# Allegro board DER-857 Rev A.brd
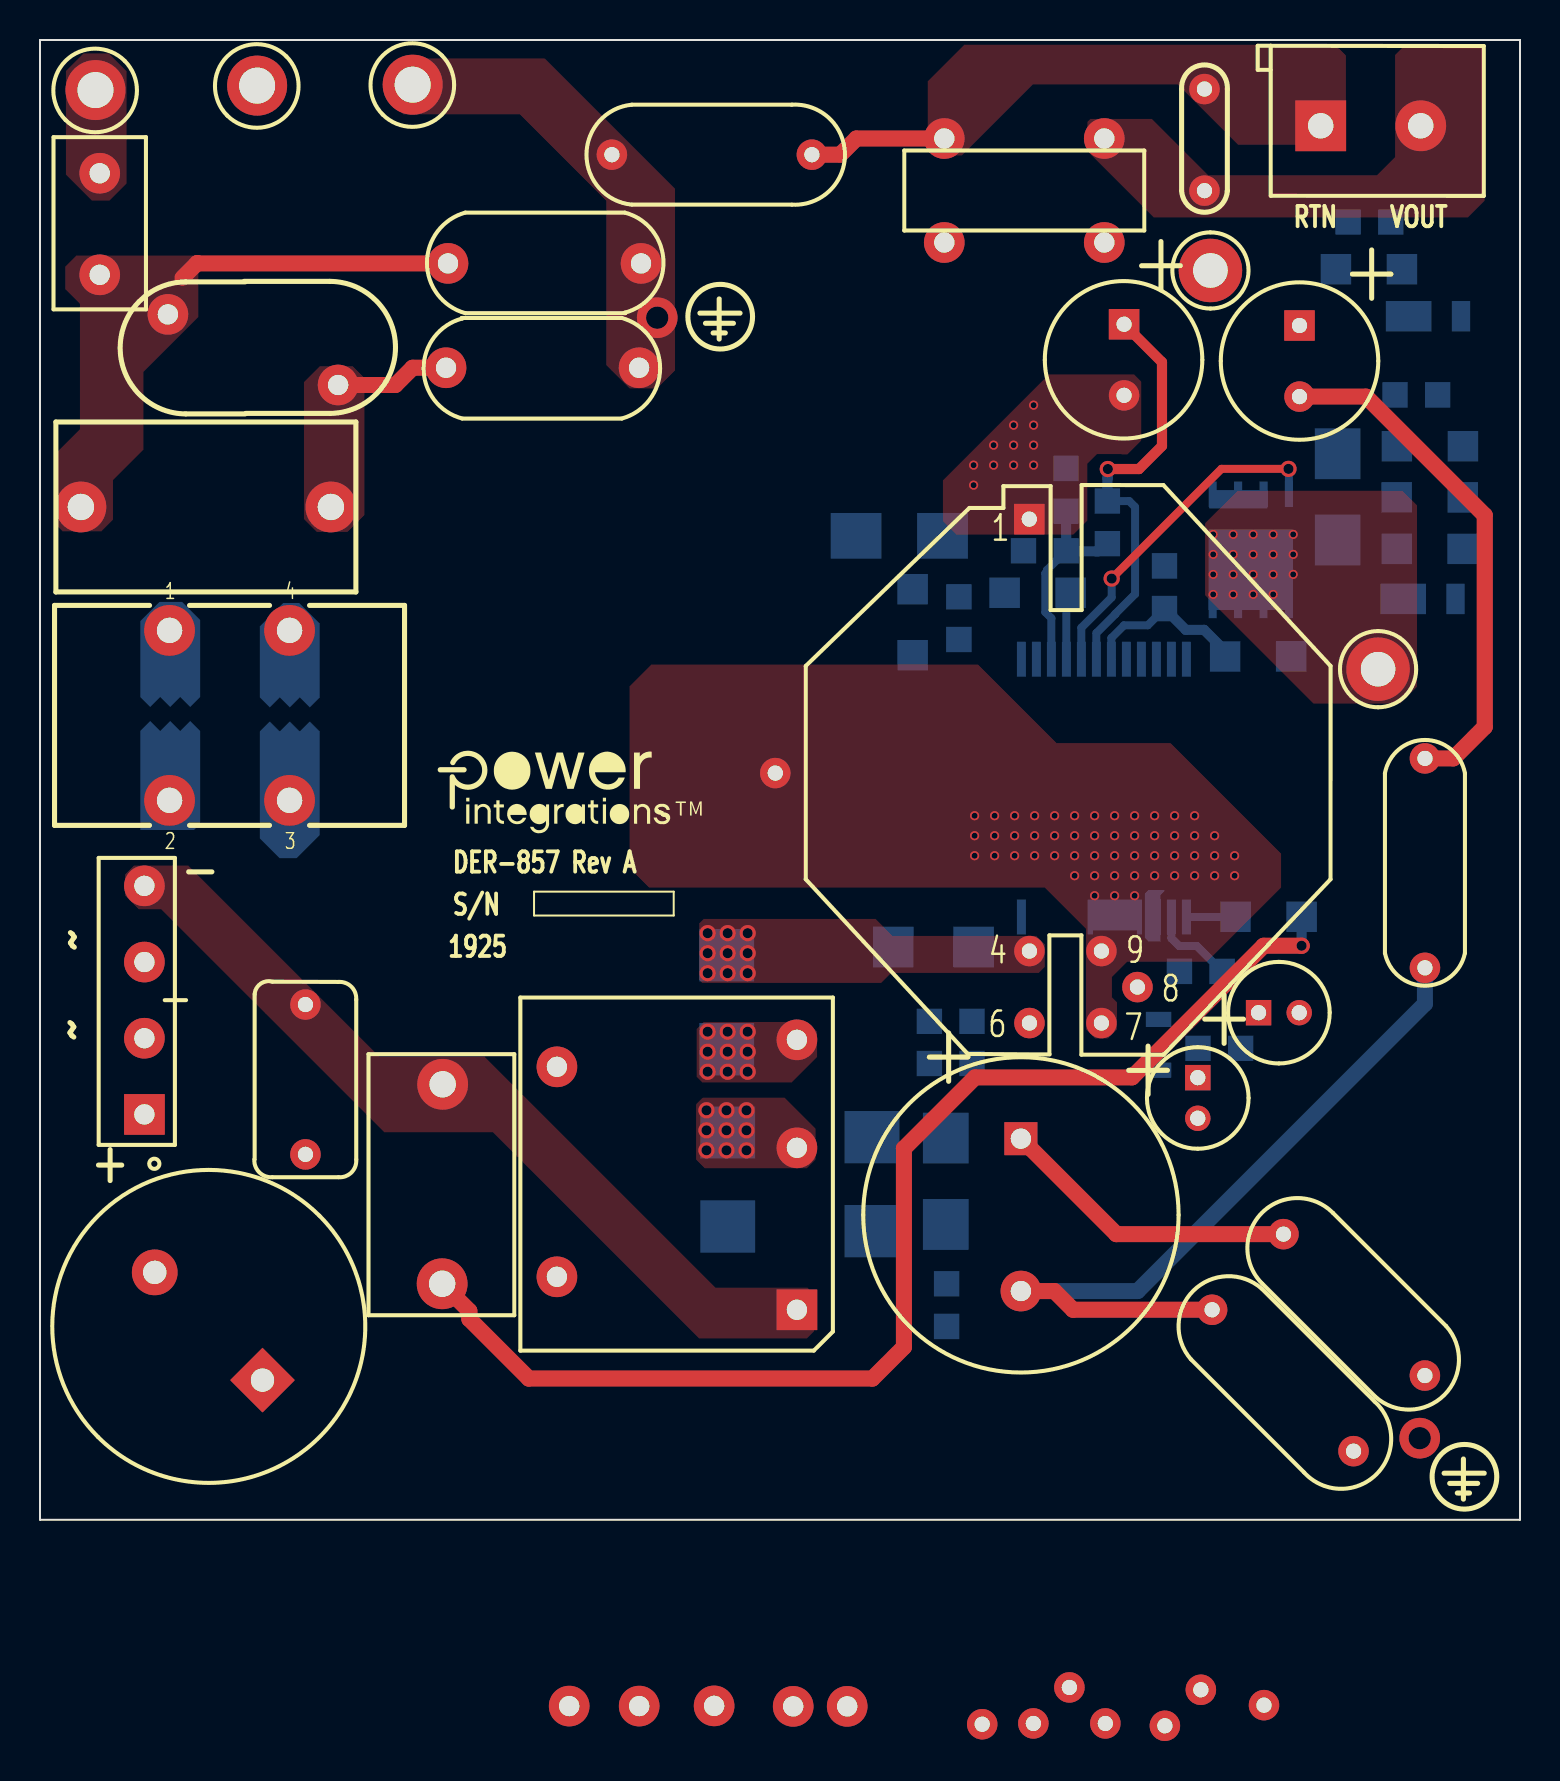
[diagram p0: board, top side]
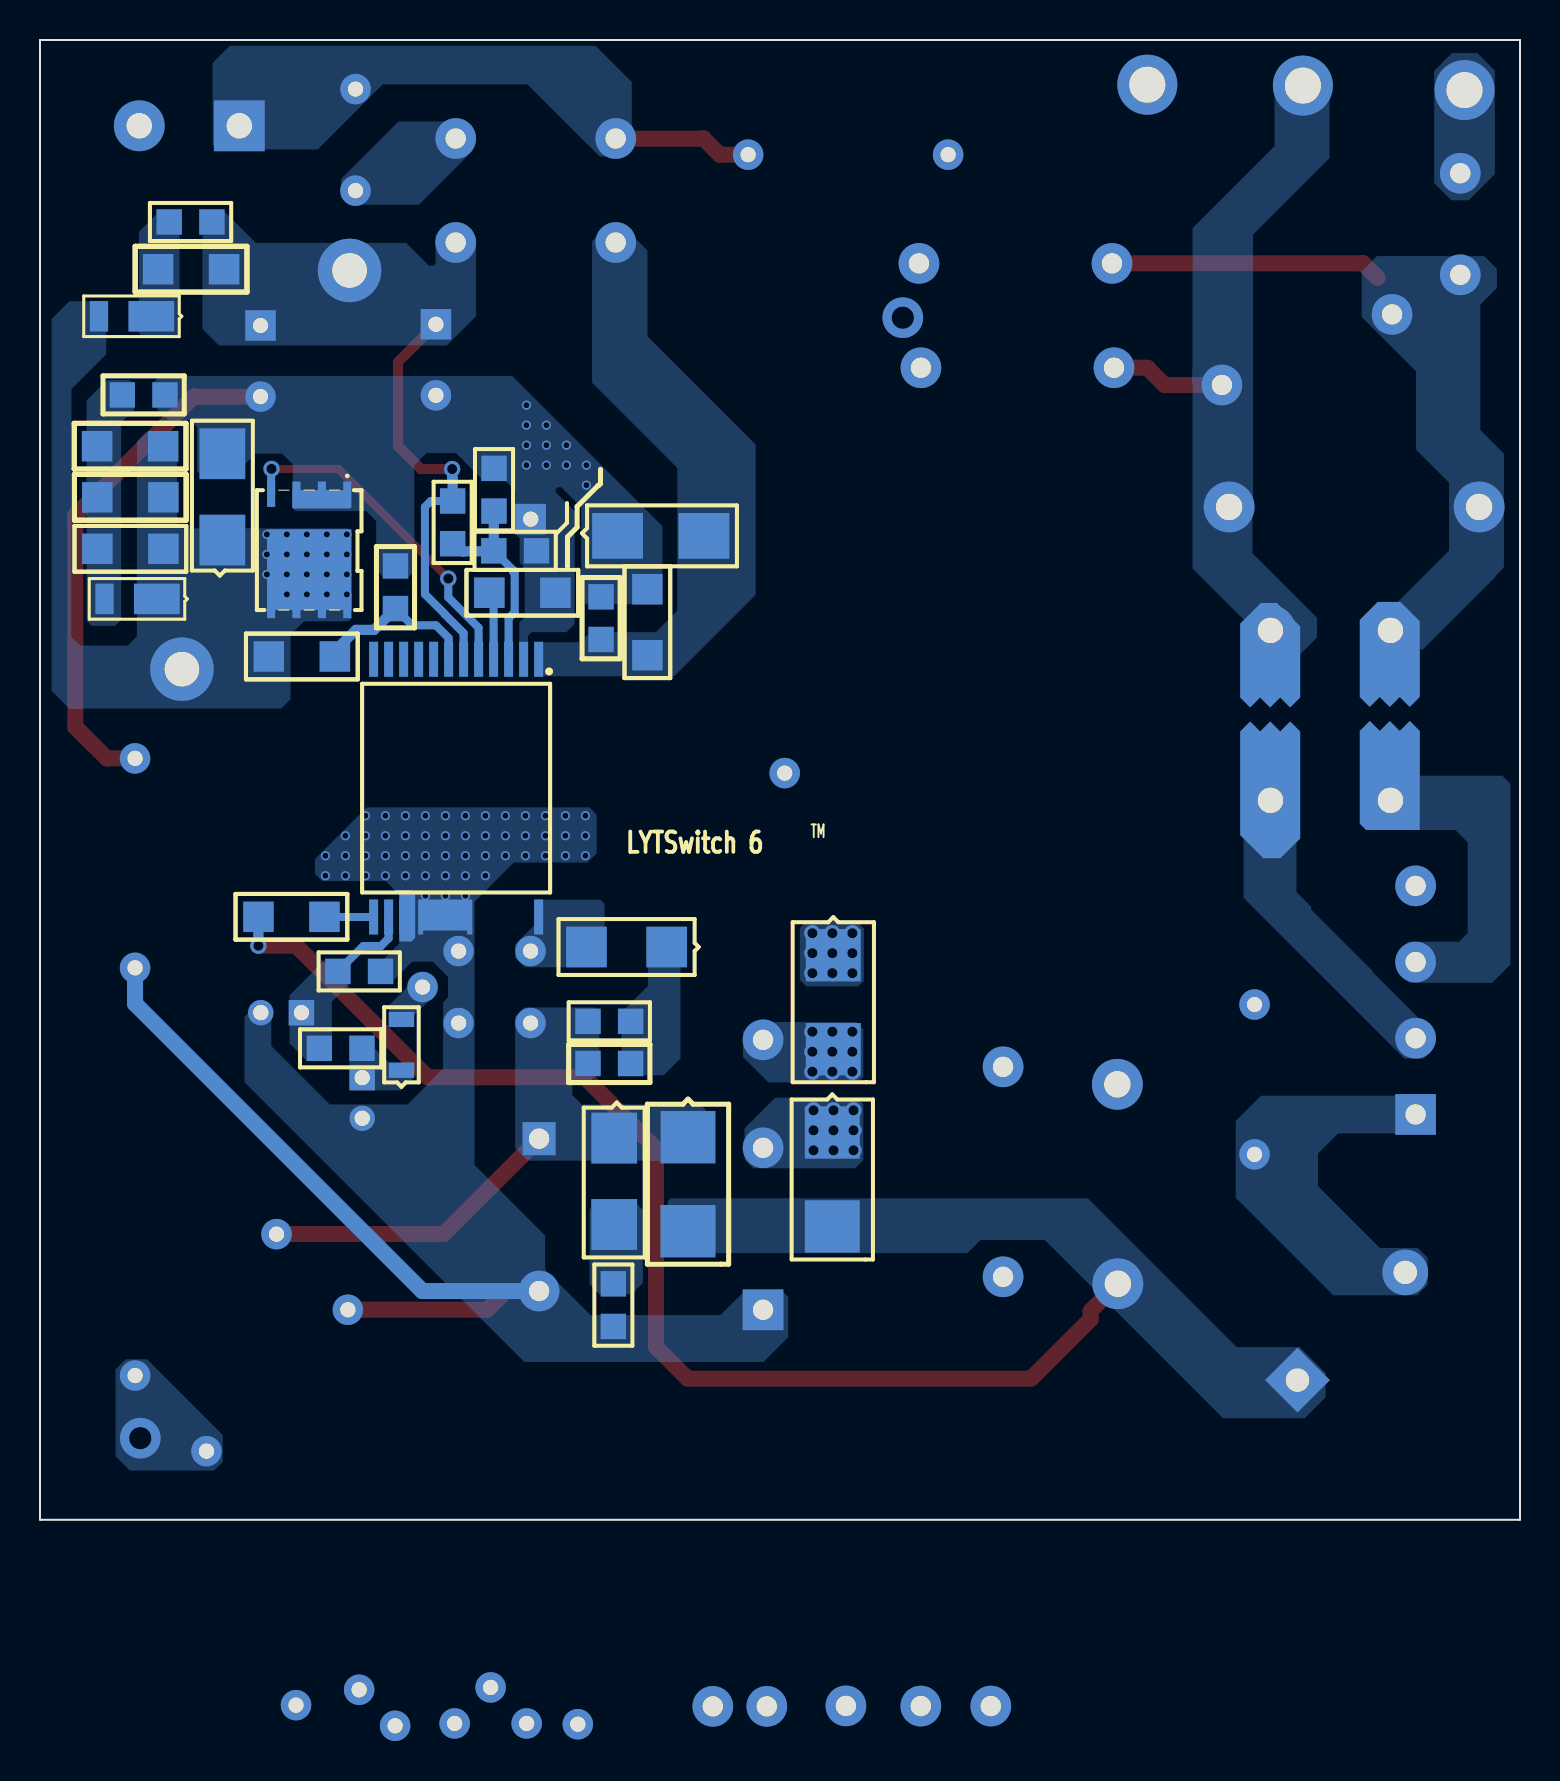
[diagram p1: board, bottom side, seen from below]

Outline 74 x 74 mm; copper layers: TOP, BOTTOM. Coordinates in mm from the lower left corner of the outline.
Outline path: 0,74 74,74 74,0 0,0 0,74

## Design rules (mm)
constraint set DEFAULT: min track width 0.508

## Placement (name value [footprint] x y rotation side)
BR1  UG4KB60TB  [PIDAXBRIDGED3K]  5.22 20.27 90 top
C1  330 nF  [PINP_XCAPRAD15X8P5X14HD040]  14.54 50.65 180 top
C3  330 nF  [PINPCR511X300LS393D40]  20.13 11.78 90 top
C4  100 uF  [PIPOLCAPCLYD630LS300040]  49.05 19.06 270 top
C9  1 nF  [PISMC0805]  44.47 24.93 0 bottom
C10  10 uF  [PIPOLCAPCLYD200LS80030]  57.89 22.11 270 top
C11  0.47 uF  [PIPOLCAPCLYD200LS80030]  60.93 25.36 0 top
C12  2200 pF  [PINPCAPRAD9P0D10P0LS030#2]  69.25 27.84 90 top
C13  2.2 uF  [PISMC1206]  48.23 46.36 0 bottom
C14  2.2 nF  [PISMC0805]  69.88 56.25 180 bottom
C16  270 uF  [PIPOLCAPCLYD320LS140030]  54.2 59.78 270 top
C18  270 uF  [PIPOLCAPCLYD320LS140030]  62.98 59.72 270 top
C19  330 pF  [PISMC0805]  49.17 48.45 0 bottom
C34  68 pF  [PINPYCAPRAD470X210LS380040]  20.3 57.61 0 top
C35  68 pF  [PINPYCAPRAD470X210LS380040]  30.05 62.83 180 top
C37  1 nF  [PINPCAPRAD200X100200030]  58.22 66.47 90 top
C41  2200 pF  [PINPCAPRAD9P0D10P0LS030]  38.59 68.27 180 top
C42  2200 pF  [PINPCAPRAD9P0D10P0LS030]  62.17 14.28 315 top
C43  2200 pF  [PINPCAPRAD9P0D10P0LS030]  65.68 3.43 135 top
C44  100 nF  [PISMC1206]  64.8 62.54 0 bottom
C45  220 nF  [PI_NP_CAP_RAD386X197X295X030]  13.27 18.27 90 top
C46  10 nF  [PISMC0805]  59.11 27.42 180 bottom
C48  100 pF  [PISMC0805]  56.23 47.7 270 bottom
D1  ES2G-13-F  [PISMDO214AA12]  34.39 19.37 270 bottom
D7  BAV21WS-7-F  [PISMSOD323]  55.93 22.48 90 bottom
D8  S1J-13-F  [PISMDSMA]  42.66 28.64 0 bottom
D16  ES2G-13-F  [PISMDO214AA12]  41.6 19.13 270 bottom
D17  ES2G-13-F  [PISMDO214AA12]  34.33 28.23 270 bottom
D18  STPS2150A  [PISMDO214AC12]  64.88 48.99 90 bottom
D21  B340A-13-F  [PISMDO214AC12]  45.12 49.2 180 bottom
D22  DFLR1200-7  [PISMDDFLR120012]  68.41 60.18 180 bottom
D23  DFLR1200-7  [PISMDDFLR120012]  68.13 46.05 180 bottom
E  GRN  [PITPKEYSTONE125X125]  18.63 71.76 315 top
F1  3.15 A  [PI_RST_MICROFUSE]  2.99 67.34 270 top
FL1  Hole_70mils  [PI_HOLE_70MIL]  58.52 62.45 0 top
FL2  Hole_70mils  [PI_HOLE_70MIL]  66.9 42.51 0 top
J2  TERMINAL BLOCK  [PI_TERM_BLOCK_2PIN_LS200]  64.04 69.71 270 top
L  WHT  [PITPKEYSTONE125X125]  10.86 71.72 315 top
L1  18mH  [PI_CMC_18MH_SUMIDA]  6.48 44.48 0 top
L4  200 uH  [PI_TOROID_DER742CMCL4]  45.21 63.07 180 top
L5  560 uh  [PI_CHOKE_RL5480-5_D2]  11.12 6.98 135 top
N  BLK  [PITPKEYSTONE125X125]  2.77 71.5 315 top
NOREF  -  []  0 0 90 top
NOREF#2  -  []  0 74 0 top
NOREF#3  -  []  -28.46 39.35 0 top
Q1  AON6250  [PISMPQFN5X6B]  58.64 51.28 0 bottom
R4  3.9 M  [PISMR1206]  59.78 30.15 0 bottom
R17  680 k  [PISMR0805]  46.6 22.82 180 bottom
R18  10 k  [PISMR0805]  57.9 23.57 0 bottom
R22  47  [PISMR1206]  59.26 43.17 0 bottom
R23  30  [PISMR1206]  67.83 48.55 0 bottom
R24  0.025  [PISMR1206]  43.63 43.23 90 bottom
R29  169 k  [PISMR0805]  53.37 50.94 270 bottom
R30  9.31 k  [PISMR0805]  51.3 50.44 90 bottom
R47  10 k  [PISMR0805]  45.33 11.8 270 bottom
R51  0.02  [PISMR0805]  45.94 44.02 90 bottom
R52  100 k  [PISMR0805]  65.41 64.9 0 bottom
R53  30  [PISMR1206]  71.14 51.13 180 bottom
R54  30  [PISMR1206]  71.15 53.69 180 bottom
RV1  140 Vac  [PIDISC500X225LS335X140040]  6.4 60.28 0 top
T1  EE19  [PI_BOBBIN_EE19_10P]  37.85 10.5 180 top
T2  RM10  [PI_BOBBIN_RM-10_12P_CLP]  49.46 50.04 270 top
U4  LYT6079C  [PI_IC_INSOP_24D]  49.07 43.03 270 bottom
VR2  BZG04-220-HM3-08  [PISMDO214AC12]  45.29 19.09 270 bottom

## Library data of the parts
BR1 = DISCRETE BRIDGE_+~~-: alternate symbols: (pidaxbridgeD3K_horz)
C1 = CAP NP: alternate symbols: (pinp_xcaprad15x8p5x14Hd040H)
C3 C9 C12-C14 C19 C34 C35 C37 C41-C46 C48 = CAP NP
C4 = CAP POL: alternate symbols: (pipolcapclyd7p5ls16x21p5D040h)
C10 = CAP POL: alternate symbols: (pipolcapclyd200ls80030h)
C11 = CAP POL: alternate symbols: (pipolcapclyd5p0x12p5ls2p0d30h)
C16 C18 = CAP POL: alternate symbols: (pipolcapclyd320ls140d30h750)
D1 D7 D8 D16 D17 D22 D23 = DIODE
D18 D21 = DIODE SCHOTTKY
E L N = TESTPOINT
F1 = FUSE: alternate symbols: (pirstmicrofusehoz)
FL1 FL2 = FlyingLead
J2 = CON2
L1 = TORRID 4P_12_43a: alternate symbols: (pi_CMC_18mH_Sumida_H)
L4 = TORRID 4P_13_24
L5 = INDUCTOR_DOT2: alternate symbols: (pi_choke_RL5480-5H_d2)
Q1 = FET_N_SGD_123_4_5678
R4 R17 R18 R22-R24 R29 R30 R47 R51-R54 = R
RV1 = VARISTOR
T1 = BEE19_10P/TF1939
T2 = BRM10_12P/PINS
U4 = LYT6
VR2 = DIODE_ZENER

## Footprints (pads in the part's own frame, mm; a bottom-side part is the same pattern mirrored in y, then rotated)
PI_BOBBIN_EE19_10P
  rect 2.032x2.032 hole 1.016: 1(0,0)
  round 2.032 hole 1.016: 2(-2.514,19.831) 3(0.186,19.831) 4(0,-8.1) 5(4.14,19.807) 6(0,-13.5) 7(12,-12.15) 8(11.387,19.817) 9(7.887,19.817) 10(12,-1.65)
PI_BOBBIN_RM-10_12P_CLP
  rect 1.524x1.524 hole 0.762: 1(0,0)
  round 1.524 hole 0.762: 2(60.34,6.779) 3(58.539,8.578) 4(21.6,0.008) 5(60.264,-2.355) 6(25.199,0.008) 7(25.199,3.607) 8(23.401,5.408) 9(21.6,3.607) 10(60.223,3.802) 11(58.422,2.004) 12(60.223,0.203) 13(59.309,11.735) 14(12.7,-12.7)
PI_CHOKE_RL5480-5_D2
  rect 2.286x2.286 hole 1.168: 1(0,0)
  round 2.286 hole 1.168: 2(7.62,0)
PI_CMC_18MH_SUMIDA
  round 2.54 hole 1.27: 1(0,0) 2(0,-8.5) 3(6,-8.5) 4(6,0)
PI_HOLE_70MIL
  round 3.175 hole 1.727: 1(0,0.025)
PI_IC_INSOP_24D
  rect 1.75x0.45 smd: 1(0,0) 2(0,-0.75) 3(0,-1.5) 4(0,-2.25) 5(0,-3) 6(0,-3.75) 7(0,-4.5) 8(0,-5.25) 9(0,-6) 10(0,-6.75) 11(0,-7.5) 12(0,-8.25) 13(12.89,-8.25) 14(12.89,-7.5) 15(12.89,-6.75) 24(12.89,0)
  custom 0.438x0.438 smd: 16(12.89,-4.67)
PI_NP_CAP_RAD386X197X295X030
  round 1.524 hole 0.762: 1(0,0) 2(7.493,0)
PI_RST_MICROFUSE
  round 2.032 hole 1.016: 1(0,0) 2(5.08,0)
PI_TERM_BLOCK_2PIN_LS200
  rect 2.54x2.54 hole 1.27: 1(0,0)
  round 2.54 hole 1.27: 2(0,5.001)
PI_TOROID_DER742CMCL4
  round 2.032 hole 1.016: 1(0,-0.8) 2(-8,-0.8) 3(0,-6) 4(-8,-6)
PIDAXBRIDGED3K
  rect 2.032x2.032 hole 1.016: 1(0,0)
  round 2.032 hole 1.016: 2(3.81,0) 3(7.62,0) 4(11.43,0)
PIDISC500X225LS335X140040
  round 2.032 hole 1.016: 1(0,0) 2(8.509,-3.531)
PINP_XCAPRAD15X8P5X14HD040
  round 2.54 hole 1.321: 1(0,0) 2(12.5,0)
PINPCAPRAD9P0D10P0LS030
  round 1.524 hole 0.762: 1(0,0) 2(10,0)
PINPCAPRAD9P0D10P0LS030#2
  round 1.524 hole 0.762: 1(-0.236,0) 2(10.236,0)
PINPCAPRAD200X100200030
  round 1.524 hole 0.762: 1(0,0) 2(5.08,0)
PINPCR511X300LS393D40
  round 2.54 hole 1.321: 1(0.025,0.025) 2(10,0)
PINPYCAPRAD470X210LS380040
  round 2.032 hole 1.016: 1(0,0) 2(9.652,0)
PIPOLCAPCLYD200LS80030
  rect 1.27x1.27 hole 0.762: 1(0,0)
  round 1.27 hole 0.762: 2(2.032,0)
PIPOLCAPCLYD320LS140030
  rect 1.524x1.524 hole 0.762: 1(0,0)
  round 1.524 hole 0.762: 2(3.556,0)
PIPOLCAPCLYD630LS300040
  rect 1.651x1.651 hole 1.016: 1(0,0)
  round 2.032 hole 1.016: 2(7.62,0)
PISMC0805
  rect 1.27x1.27 smd: 1(0,0) 2(2.134,0)
PISMC1206
  rect 1.524x1.524 smd: 1(0,0) 2(3.302,0)
PISMDDFLR120012
  rect 2.286x1.524 smd: 1(-0.025,0)
  rect 0.914x1.524 smd: 2(-2.642,0)
PISMDO214AA12
  rect 2.616x2.743 smd: 1(0,0) 2(4.699,0)
PISMDO214AC12
  rect 2.54x2.286 smd: 1(0,0) 2(4.318,0)
PISMDSMA
  rect 2.032x2.032 smd: 1(0,0) 2(4.013,0)
PISMPQFN5X6B
  rect 0.406x1.27 smd: 1(0,0) 2(1.27,0) 3(2.54,0) 4(3.81,0)
  rect 0.406x1.219 smd: 5(3.81,5.588) 6(2.54,5.588) 7(1.27,5.588) 8(0,5.588)
PISMR0805
  rect 1.27x1.27 smd: 1(0,0) 2(2.134,0)
PISMR1206
  rect 1.524x1.524 smd: 1(0,0) 2(3.302,0)
PISMSOD323
  rect 0.762x1.27 smd: 1(0,0) 2(2.54,0)
PITPKEYSTONE125X125
  round 3 hole 1.8: 1(0,0)

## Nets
GND: C12.2 C13.1 C14.2 C16.2 C18.2 C19.1 C48.1 D18.2 D21.1 Q1.1 Q1.2 Q1.3(S3) R24.2 R30.2 R51.2 T2.1 U4.2
GND_EARTH: C34.2 C35.1 C41.2 C42.2 C43.1 E.1
NC8: U4.8
NC9: U4.9
NC10: U4.10
NC11: U4.11
NC12: U4.12
NC15: U4.15
N10967118: C10.1 D7.1 R18.1
N10967272: D8.2 D17.1 T2.4 U4.24
N10967292: C4.1 C9.2 C42.1 D16.1 R17.1 T2.6 VR2.1
N10967352: C11.1 C46.1 R18.2 U4.14
N10967360: C19.2 R29.2 R30.1 U4.3
N10967588: C16.1 C18.1 C44.1 FL1.1 L4.2 R29.1 R52.1 U4.6
N10967640: D18.1 D22.2 D23.1 FL2.1 Q1.5 Q1.6 Q1.7 Q1.8 R22.2 R23.1 R53.2 R54.2
N10968210: C14.1 D23.2 R23.2 R53.1 R54.1
N10968562: BR1.4 C3.2 C4.2 C10.2 C11.2 C12.1 C43.2 C45.2 C46.2 R47.2 T1.1 T2.7 T2.9 T2.14 U4.16
N10971255: BR1.3(AC2) L1.2
N10975943: C9.1 D8.1 R17.2
N11015169: Q1.4 U4.5
N11207739: C1.1 C34.1 L.1 L1.4 RV1.2
N11207756: C1.2 C35.2 F1.2 L1.1 RV1.1
N11317958: R4.1 U4.13(VPIN)
N11319179: C13.2 U4.4
N11459390: C3.1 D1.2 D16.2 L5.1 R4.2
N11460031: BR1.1 C45.1 L5.2
N11465077: F1.1 N.1
N11478836: R47.1 VR2.2
N11926309: C37.2 C41.1 J2.1 L4.3
N11926313: C37.1 J2.2 L4.4
N11931425: D7.2 T2.8
N11945881: D21.2 L4.1 R24.1 R51.1 U4.1
N12237173: D17.2 T1.6
N12296601: BR1.2 L1.3
N12434563: C44.2 D22.1 R52.2
N12457252: D1.1 T1.4
N12494744: C48.2 R22.1 U4.7

Pads without a net: T1 2 3 5 7 8 9 10; T2 2 3 5 10 11 12 13

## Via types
v1: diameter 2.032, hole 1.118, TOP to BOTTOM, 2 vias
v2: diameter 0.813, hole 0.508, TOP to BOTTOM, 31 vias
v3: diameter 0.457, hole 0.305, TOP to BOTTOM, 81 vias

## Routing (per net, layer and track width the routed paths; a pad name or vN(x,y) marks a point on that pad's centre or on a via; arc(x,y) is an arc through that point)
GND: length 25.9
  TOP w0.8: C18.2 66.3,56.17 72.24,50.23 72.24,39.65 70.66,38.07 C12.2
  vias: v3(46.68,52.74) v3(46.68,51.74) v3(47.68,53.74) v3(47.68,52.74) v3(48.68,54.74) v3(48.68,53.74) v3(48.68,52.74) v3(49.68,55.74) v3(49.68,54.74) v3(49.68,53.74) v3(49.68,52.74)
GND_EARTH:
  vias: v1(30.86,60.11) v1(68.99,4.08)
N10967272:
  vias: v2(33.38,29.33) v2(33.38,28.33) v2(33.38,27.33) v2(34.38,29.33) v2(34.38,28.33) v2(34.38,27.33) v2(35.38,29.33) v2(35.38,28.33) v2(35.38,27.33)
N10967292: length 15.1
  TOP w0.8: C42.1 53.82,14.28 C4.1
N10967352: length 4.3
  BOTTOM w0.4: U4.14 56.57,29.08 56.95,28.69 57.84,28.69 C46.1
N10967360: length 10.2
  BOTTOM w0.4: C19.2 50.35,47.5 50.35,47.42 50.27,47.33 50.27,45.39 50.57,45.09 U4.3
  BOTTOM w0.508: R29.2 53.24,48.81 52.86,48.43 51.33,48.43 C19.2 51.31,50.43 R30.1
N10967588: length 21.6
  TOP w0.508: C16.1 56.1,57.89 56.1,53.7 54.95,52.54 v2(53.39,52.54)
  BOTTOM w0.4: U4.6 52.82,44.34 53.76,45.29 53.76,45.3 54.75,46.29 54.75,50.65 54.46,50.94 R29.1
  BOTTOM w0.508: R29.1 53.37,52.09 53.39,52.11 v2(53.39,52.54)
N10967640:
  vias: v3(58.66,49.28) v3(58.66,48.28) v3(58.66,47.28) v3(58.66,46.28) v3(59.66,49.28) v3(59.66,48.28) v3(59.66,47.28) v3(59.66,46.28) v3(60.66,49.28) v3(60.66,48.28) v3(60.66,47.28) v3(60.66,46.28) v3(61.66,49.28) v3(61.66,48.28) v3(61.66,47.28) v3(61.66,46.28) v3(62.66,49.28) v3(62.66,48.28) v3(62.66,47.28)
N10968562: length 37.9
  TOP w0.8: C43.2 51.65,10.5 50.72,11.44 C4.2
  BOTTOM w0.8: C4.2 54.88,11.44 69.25,25.8 C12.1
  vias: v3(46.73,35.21) v3(46.73,34.21) v3(46.73,33.21) v3(47.73,35.21) v3(47.73,34.21) v3(47.73,33.21) v3(48.73,35.21) v3(48.73,34.21) v3(48.73,33.21) v3(49.73,35.21) v3(49.73,34.21) v3(49.73,33.21) v3(50.73,35.21) v3(50.73,34.21) v3(50.73,33.21) v3(51.73,35.21) v3(51.73,34.21) v3(51.73,33.21) v3(51.73,32.21) v3(52.73,35.21) v3(52.73,34.21) v3(52.73,33.21) v3(52.73,32.21) v3(52.73,31.21) v3(53.73,35.21) v3(53.73,34.21) v3(53.73,33.21) v3(53.73,32.21) v3(53.73,31.21) v3(54.73,35.21) v3(54.73,34.21) v3(54.73,33.21) v3(54.73,32.21) v3(54.73,31.21) v3(55.73,35.21) v3(55.73,34.21) v3(55.73,33.21) v3(55.73,32.21) v3(56.73,35.21) v3(56.73,34.21) v3(56.73,33.21) v3(56.73,32.21) v3(57.73,35.21) v3(57.73,34.21) v3(57.73,33.21) v3(57.73,32.21) v3(58.73,34.21) v3(58.73,33.21) v3(58.73,32.21) v3(59.73,33.21) v3(59.73,32.21)
N11015169: length 17.1
  TOP w0.4: v2(62.42,52.55) 59.07,52.55 v2(53.58,47.07)
  BOTTOM w0.4: v2(62.42,52.55) 62.45,52.53 Q1.4 ; v2(53.58,47.07) 53.58,46.13 52.07,44.61 U4.5
N11207739: length 5.8
  TOP w0.8: RV1.2 17.77,56.75 18.63,57.61 C34.1
N11207756: length 13.6
  TOP w0.8: C35.2 7.88,62.83 7.88,62.82 7.86,62.84 7.12,62.11
N11317958: length 2.5
  BOTTOM w0.4: R4.1 59.68,30.15 59.67,30.14 U4.13
N11319179: length 3.4
  BOTTOM w0.4: U4.4 51.32,46.15 C13.2
N11459390: length 61.4
  TOP w0.8: C3.1 21.47,10.44 21.47,10.03 24.44,7.06 41.62,7.06 43.2,8.64 43.2,18.57 46.75,22.12 54.6,22.12 61.18,28.71 v2(63.08,28.71)
  BOTTOM w0.508: R4.2 v2(63.08,28.71)
N11926309: length 7
  TOP w0.8: C41.1 40.01,68.27 40.82,69.07 L4.3
N12237173:
  vias: v2(33.38,24.41) v2(33.38,23.41) v2(33.38,22.41) v2(34.38,24.41) v2(34.38,23.41) v2(34.38,22.41) v2(35.38,24.41) v2(35.38,23.41) v2(35.38,22.41)
N12457252:
  vias: v2(33.32,20.48) v2(33.32,19.48) v2(33.32,18.48) v2(34.32,20.48) v2(34.32,19.48) v2(34.32,18.48) v2(35.32,20.48) v2(35.32,19.48) v2(35.32,18.48)
N12494744: length 8.5
  BOTTOM w0.4: U4.7 53.57,44.1 54.2,44.73 55.39,44.73 C48.2
  BOTTOM w0.508: C48.2 57.29,44.5 58.21,44.5 59.26,43.45 R22.1

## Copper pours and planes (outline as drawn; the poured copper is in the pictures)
GND on BOTTOM (solid shape): 61.38,50.57 58.46,50.57 58.46,51.49 61.38,51.49
GND on TOP: 54.7,57.28 50.44,57.28 45.15,51.98 45.15,49.93 45.81,49.27 51.66,49.27 52.37,49.97 52.37,52.81 52.85,53.29 54.07,53.29 54.08,53.28 54.37,53.28 55.06,53.96 55.06,56.92
GND on BOTTOM: 50.04,42.18 49.61,42.18 49.61,44.19 49.4,44.39 47.68,44.39 47.27,44.8 47.27,50.44 48.21,51.37 48.21,51.53 48.11,51.63 47.93,51.63 46.94,50.64 46.94,46.04 46.69,45.79 42.88,45.79 42.88,49.68 50.39,57.2 65.75,57.2 65.76,57.2 68,57.2 68.28,56.92 68.28,55.68 67.59,54.99 66.5,54.99 66.14,54.64 66.14,52.43 65.9,52.2 63.92,52.2 63.87,52.25 63.87,52.68 63.24,53.31 61.89,53.31 61.36,52.78 61.36,50.57 61.23,50.44 57.7,50.44 57.19,49.94 57.19,47.51 56.74,47.07 55.65,47.07 55.29,47.43 55.29,52.73 54.68,53.34 53.2,53.34 51.9,52.03 50.8,52.03 50.22,51.44 50.22,49.29 50.01,49.09 50.01,47.79 49.76,47.54 49.76,45.15 50.04,44.87
GND_EARTH on TOP: 18.16,70.28 23.99,70.28 28.31,65.96 28.31,57.74 29.48,56.58 30.86,56.58 31.75,57.47 31.75,66.56 25.24,73.08 18.03,73.08 17.4,72.44 17.4,71.04
GND_EARTH on BOTTOM: 69.71,8.03 68.65,8.03 64.86,4.24 64.86,2.9 65.29,2.46 69.51,2.46 70.22,3.17 70.22,7.52
N10967118 on BOTTOM: 58.52,24.2 58.52,21.48 55.93,21.48 55.3,22.11 55.3,22.85 56.54,22.85 57.28,23.59 57.28,24.2
N10967272 on TOP: 42.62,29.2 49.81,29.2 50.24,28.77 50.24,27.65 49.94,27.35 42.56,27.35 42.06,26.85 33.11,26.85 32.96,27 32.96,29.82 33.19,30.05 41.77,30.05
N10967272 on BOTTOM: 49.76,27.63 46.02,27.63 45.77,27.88 45.77,30.8 45.97,31 49.28,31 49.28,29.73 50.24,28.77 50.24,28.11
N10967272 on BOTTOM: 32.81,29.57 32.81,26.95 33.09,26.67 35.68,26.67 36.01,27 36.01,29.59 35.63,29.97 33.21,29.97
N10967292 on BOTTOM: 46.91,20.77 47.39,21.24 47.39,21.89 47.29,22 46.45,22 46.04,22.4 46.04,25.37 46.29,25.62 49.78,25.62 50.24,25.16 50.24,18.58 49.62,17.96 41.04,17.96 40.71,18.29 40.71,20.5 40.98,20.77
N10967352 on BOTTOM: 58.5,28.03 58.5,26.81 59.41,25.9 59.41,22.95 60.66,22.95 61.52,23.82 61.52,26.23 59.72,28.03
N10967588 on BOTTOM: 55.69,63.86 54.55,62.71 54.32,62.71 54.22,62.81 54.22,64.26 53.79,64.69 52.77,64.69 52.2,64.12 52.2,60.19 53.66,58.72 65.05,58.72 65.88,59.55 65.88,65.2 65.65,65.43 64.79,65.43 63.21,63.86
N10967640 on BOTTOM (solid shape): 62.65,45.49 58.43,45.49 58.43,49.53 62.65,49.53
N10967640 on TOP: 58.26,49.83 58.26,46.23 63.67,40.82 68.01,40.82 68.85,41.66 68.85,50.72 68.11,51.46 59.88,51.46
N10967640 on BOTTOM: 61.47,41.03 61.94,40.56 72.53,40.56 73.42,41.45 73.42,60.05 72.53,60.93 70.89,60.93 70.69,60.73 70.69,58.28 72.43,56.54 72.43,44.15 72,43.71 69.61,43.71 69.15,44.17 69.15,53.93 68.71,54.38 67.39,54.38 67.15,54.14 67.15,49.86 66.87,49.58 58.59,49.58 58.44,49.43 58.44,45.03 58.54,44.93 60.8,44.93 61.47,44.26
N10968210 on BOTTOM: 69.94,45.01 70.25,44.7 71.42,44.7 71.67,44.96 71.67,55.98 70.65,57 69.82,57 69.81,56.99 69.51,56.99 69.29,56.77 69.29,55.52 69.94,54.86
N10968562 on BOTTOM (solid shape): 56.03,31.26 56.03,28.92 55.42,28.92 55.24,29.1 55.24,31.31 55.42,31.49 56.26,31.49
N10968562 on TOP: 4.94,30.53 6.06,30.53 17.21,19.38 22.65,19.38 32.96,9.07 38.34,9.07 38.7,9.42 38.7,11.28 38.37,11.61 33.77,11.61 22.22,23.16 16.96,23.16 7.41,32.72 4.7,32.72 4.25,32.27 4.25,31.22
N10968562 on TOP: 53.39,24.07 52.76,24.07 52.3,24.53 52.3,29.56 50.24,31.61 30.45,31.61 29.48,32.59 29.48,41.68 30.56,42.76 46.9,42.76 50.83,38.84 56.53,38.84 62.05,33.32 62.05,31.61 58.34,27.91 54.36,27.91 53.59,27.14 53.59,26.13 53.85,25.87 53.85,24.53
N10968562 on BOTTOM: 52.27,30.9 50.31,32.87 46.63,32.87 46.17,33.32 46.17,35.27 46.52,35.63 57.66,35.63 60.25,33.04 60.25,32.3 59.89,31.94 56.72,31.94 56.03,31.26 56.03,28.82 56.82,28.03 57.58,28.03 57.58,26.81 56.49,26.81 55.4,27.91 54.36,27.91 53.59,27.14 53.59,26.13 53.85,25.87 53.85,22.55 55.63,20.77 59.51,20.77 62.43,23.69 62.43,25.39 62.69,25.64 63.3,25.64 63.78,25.16 63.78,21.89 49.78,7.89 37.82,7.89 36.59,9.12 36.59,11.15 36.87,11.43 38.78,11.43 39.97,10.24 46.47,10.24 48.74,12.51 48.74,14.21 52.27,17.75
N10971255 on BOTTOM (solid shape): 8.01,39.45 8.01,34.81 7.7,34.49 5.01,34.49 5.01,38.95 5.01,38.95 5.01,39.45 5.51,39.95 6.01,39.45 6.51,39.95 7.01,39.45 7.51,39.95
N10971255 on BOTTOM: 1.39,26.85 5.54,26.85 5.92,27.23 5.92,28.57 5.59,28.91 3.05,28.91 2.62,29.34 2.62,33.88 3.23,34.49 7.24,34.49 7.8,35.05 7.8,36.65 7.24,37.21 0.88,37.21 0.48,36.81 0.48,27.76
N10975943 on BOTTOM: 43.45,29.51 42.13,29.51 41.98,29.36 41.98,23.06 42.82,22.23 44.8,22.23 44.92,22.35 44.92,25.37 43.6,26.7 43.6,29.36
N11207739 on BOTTOM (solid shape): 13.99,44.81 13.99,41.12 13.49,40.62 12.99,41.12 12.49,40.62 11.99,41.12 11.49,40.62 10.99,41.12 10.99,44.68 12.16,45.85 12.95,45.85
N11207739 on TOP: 13.2,50.04 13.83,49.4 15.38,49.4 16.22,50.24 16.22,57.1 15.64,57.68 13.99,57.68 13.2,56.9
N11207739 on BOTTOM: 9.53,68.09 13.35,64.26 13.35,57.05 13.94,56.46 16.02,56.46 16.37,56.82 16.37,64.59 12.28,68.69 12.28,72.23 11.61,72.9 10.03,72.9 9.53,72.39
N11207739 on BOTTOM: 15.26,58.75 14.09,58.75 13.35,58.01 13.35,50.29 13.38,50.27 13.38,48.34 10.15,45.11 10.15,44.12 10.99,43.28 12.08,43.28 16.37,47.57 16.37,57.63
N11207756 on BOTTOM (solid shape): 8.01,45 8.01,41.15 7.51,40.65 7.01,41.15 6.51,40.65 6.01,41.15 5.51,40.65 5.01,41.15 5.01,44.93 5.98,45.9 7.11,45.9
N11207756 on TOP: 7.86,63.22 1.82,63.22 1.26,62.66 1.26,61.54 2,60.81 2,54.53 0.75,53.29 0.75,49.81 1.13,49.43 3.06,49.43 3.65,50.01 3.65,51.99 5.17,53.52 5.17,57.4 7.92,60.15 7.92,63.17
N11207756 on BOTTOM: 1.79,63.2 7.15,63.2 7.92,62.43 7.92,60.15 5.2,57.43 5.2,53.52 3.55,51.87 3.55,48.46 6.57,45.44 6.57,44.3 5.78,43.51 4.87,43.51 1.24,47.14 1.24,47.19 0.8,47.62 0.8,53.31 1.98,54.5 1.98,60.77 1.16,61.59 1.16,62.56
N11459390 on BOTTOM: 42.46,16.08 21.61,16.08 14.16,8.64 11.01,8.64 9.72,7.34 9.72,6.12 10.76,5.08 14.85,5.08 23.77,14 26.97,14 27.63,13.34 42.13,13.34 42.61,13.82 42.61,15.93
N11460031 on BOTTOM: 4.39,21.21 12.94,21.21 14.21,19.94 14.21,16.1 9.34,11.23 5.15,11.23 4.61,11.76 4.61,13.11 5.1,13.59 7,13.59 10.1,16.69 10.1,18.31 9.08,19.33 4.39,19.33
N11465077 on TOP: 4.33,72.43 4.33,66.83 3.47,65.96 2.61,65.96 1.29,67.28 1.29,72.45 2.17,73.33 3.43,73.33
N11465077 on BOTTOM: 4.29,72.45 4.29,66.85 3.43,65.99 2.57,65.99 1.26,67.3 1.26,72.47 2.14,73.35 3.39,73.35
N11478836 on BOTTOM: 46.12,15.93 44.29,15.93 43.86,15.49 43.86,11.84 44.42,11.28 46.02,11.28 46.52,11.79 46.52,15.52
N11926309 on TOP: 59.91,68.76 65.14,68.76 65.29,68.91 65.29,73.23 64.94,73.58 64.91,73.58 64.74,73.76 46.22,73.76 44.39,71.93 44.39,68.61 44.77,68.22 46.09,68.22 49.65,71.78 56.89,71.78
N11926309 on BOTTOM: 44.8,68.17 46.02,68.17 49.62,71.78 56.86,71.78 60.11,68.53 65.14,68.53 65.37,68.76 65.37,72.85 64.51,73.71 46.22,73.71 44.42,71.91 44.42,68.55
N11926313 on TOP: 58.41,67.23 66.84,67.23 67.76,68.15 67.76,73.25 68.22,73.71 72,73.71 72.23,73.48 72.23,65.96 71.39,65.13 55.69,65.13 52.37,68.45 52.37,69.9 52.52,70.05 55.59,70.05
N11926313 on BOTTOM: 52.62,69.72 52.62,68.2 55.06,65.76 58.59,65.76 58.94,66.12 58.94,67.06 56.07,69.93 52.82,69.93
N11931425 on BOTTOM: 56.54,24.65 55.3,24.65 55.3,25.21 54.25,26.25 54.25,26.99 54.52,27.26 55.02,27.26 56.54,25.73
N11945881 on BOTTOM: 42.14,45.46 43.21,44.39 46.48,44.39 46.99,43.88 49.28,43.88 49.28,42.18 42.29,42.18 38.22,46.25 38.22,53.77 43.63,59.18 43.63,63.47 44.92,64.77 45.56,64.77 46.4,63.93 46.4,56.86 42.14,52.6
N12237173 on TOP: 33.19,24.89 38.37,24.89 38.85,24.41 38.85,23.14 37.58,21.87 33.11,21.87 32.83,22.15 32.83,24.54
N12237173 on BOTTOM: 38.37,24.89 33.19,24.89 32.83,24.54 32.83,22.15 33.11,21.87 37.58,21.87 38.85,23.14 38.85,24.41
N12296601 on BOTTOM (solid shape): 13.99,39.42 13.99,34.24 12.84,33.09 11.97,33.09 10.99,34.07 10.99,38.92 10.99,38.92 10.99,39.42 11.49,39.92 11.99,39.42 12.49,39.92 12.99,39.42 13.49,39.92
N12296601 on BOTTOM: 5.78,23.06 4.8,23.06 4.6,23.27 4.6,24.62 7.36,27.38 7.36,27.43 10.44,30.52 10.44,30.66 11.18,31.39 11.18,36.55 11.66,37.03 12.21,37.03 12.23,37.06 13.31,37.06 13.82,36.55 13.82,31.1
N12434563 on BOTTOM: 67.02,65.35 67.02,59.36 67.22,59.16 68.85,59.16 69.05,59.36 69.05,64.41 68.09,65.38 67.05,65.38
N12457252 on TOP: 37.23,21.11 38.78,19.56 38.78,18.01 38.34,17.58 33.24,17.58 32.81,18.01 32.81,20.78 33.14,21.11
N12457252 on BOTTOM: 33.16,21.11 37.23,21.11 38.78,19.56 38.78,18.01 38.34,17.58 33.24,17.58 32.83,17.98 32.83,20.78

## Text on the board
Ref Des/Silkscreen Bottom: TM | LYTSwitch 6
Ref Des/Silkscreen Top: 1925 | DER-857 Rev A | S/N | RTN | VOUT
User.5: 1.  THROUGH HOLES ARE PLATED THROUGH. | EXCEPTIONS WILL BE NOTED IN DRILL CHART "NOTE". | 2.  MATERIAL: BASE MATERIAL LAMINATED EPOXY | UL APPROVED MANUFACTURED SOURCE FOR FR4. | 3.  SOLDER PLATE WILL BE RoHS COMPLIANT. | 4.  SOLDER MASK LPI (LIQUID PHOTO IMAGEABLE) BOTH SIDES. COLOR GREEN. | SOLDER MASK (REGISTRATION) -0/+0.003" | 5.  SILKSCREEN TOP/BOTTOM SIDE. COLOR WHITE. (MIN.WIDTH 0.005" MAX.WIDTH 0.010") | 6.  FINISH TO BE SMOBC. | 7.  LF HASL. | 8.  BOARD DIMENSION +/- 0.005" | 9.  DRILL TOLERANCE +/- 0.003" | 10. TRACE WIDTH UNDER 0.010" +/- 0.002" | TRACE WIDTH OVER 0.011" +/- 0.005" | 11. TRACE SPACE +/- 0.003" | 12. MATERIAL FR4 COPPER 2 OZ BOARD THICKNESS 0.062" | DELETE THESE HOLES: | NOTES: UNLESS OTHERWISE SPECIFIED
User.8: FIGURE | FINISHED_SIZE | 12.0 | 20.0 | 30.0 | 40.0 | 44.0 | 46.0 | 50.0 | 52.0 | 68.0 | 70.866 | DRILL CHART: TOP to BOTTOM | ALL UNITS ARE IN MILS | PLATED | QTY | 81 | 31 | 16 | 12 | 6 | 13 | 5 | 4 | 2 | 1 | 3
